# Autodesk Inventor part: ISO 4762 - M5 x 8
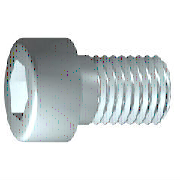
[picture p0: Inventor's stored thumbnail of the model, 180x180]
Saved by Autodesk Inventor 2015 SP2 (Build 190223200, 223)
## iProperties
IsCustomPart: 0
Created: 2012-02
Part Number: ISO 4762 - M5 x 8
Material: Edelstahl, 440C
Description: Innensechskantschraube
Document SubType Name: Modeling
Standard: ISO 4762
Designer: Dan
Standard Revision: 1998
Standards Organization: DIN
Language: de-DE
Size Designation: M5 x 8
Categories: <MemberInstance><Categories><Category DisplayName="Verbindungselemente" InternalName="e4da775c-781d-43d5-af7c-5136215cf5a6" Mnemonic="FSTN"><Category DisplayNam
Density: 7.75 g/cm^3
Appearance: Halbpoliert
Author: Dan
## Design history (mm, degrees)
sketch "Skizze1"
  geometry: L1 (-1.167, 0)-(8, 0); L2 (8, 0)-(8, 2.5); L3 (8, 2.5)-(2, 2.5); L4 (2, 2.5)-(1.509, 2.5); L5 (1.509, 2.5)-(0, 2.5); L6 (0, 2.5)-(0, 4.25); L7 (0, 4.25)-(-5, 4.25); L8 (-5, 4.25)-(-5, 2.309); L9 (-5, 2.309)-(-2.5, 2.309); L10 (-2.5, 2.309)-(-1.167, 0); L11 (-7.6, 0)-(10.6, 0) reference; L12 (0, -0.85)-(0, 5.1) reference; L13 (2, 2.5)-(0, 2.5)
  constraints: 22 end point, 6 parallel, 2 collinear, 2 perpendicular, 1 horizontal, 1 point on line
  dimensions: "d1" = 6 distance from line of L3.end L2 (= GEL); "d2" = 0.49086 distance of L4.end L3.end (computed from GAL); "d3" = 5 distance between parallel lines of L8 L6 (= KOH); "d4" = 2.5 distance of L8.end L9.end (= INTI); "d5" = 60 deg angle of L10 L1; "d6" = 5 diameter of L3 L1 (= GD); "d7" = 5 diameter of L5 L1 (= BDM); "d8" = 4.6188 diameter of L9 L1 (= 1.1547 x SW); "d9" = 8.5 diameter of L7 L1 (= KOD); "d26" = 8 distance between parallel lines of L12 L2 (= NLG)
revolve "Körper" sketch "Skizze1" stored, may be unused: angle "d10" = 90 deg
sketch "Skizze2"
  geometry: L1 (0, -5.95)-(0, 5.95) reference; L2 (-5.95, 0)-(5.95, 0) reference; L3 (2.309, 0)-(1.155, -2); L4 (1.155, -2)-(-1.155, -2); L5 (-1.155, -2)-(-2.309, 0); L6 (-2.309, 0)-(-1.155, 2); L7 (-1.155, 2)-(1.155, 2); L8 (1.155, 2)-(2.309, 0); 2 further points
  constraints: 12 end point, 1 coincident, 1 horizontal alignment, 1 point on line, 12 other
extrude "Loch" join sketch "Skizze2" stored distance "d11" = 10; taper "d12" = 0 deg
workplane "Work Plane1"
fillet "Fillet2" dims "d30" = 0.1 (= R)
body "Solid1"
fillet "Rundung1" dims "d17" = 0.5 (= RR)
feature "Gewinde" dims "d13" = 6 (= GEL), "d14" = 0
chamfer "Fase1" distance "d15" = 0.49076 (= -0.5 x SPD + 0.5 x GD); stored, may be unused: second distance "d16" = 0.49076 (= GUL), angle "d27" = 45 deg
other parameters: "GD" = 5 [user parameter; used in 2 equation terms], "NLG" = 8 [user parameter; used in 1 equation term], "GEL" = 6 [user parameter; used in 2 equation terms], "KOD" = 8.5 [user parameter; used in 1 equation term], "KOH" = 5 [user parameter; used in 1 equation term], "INTI" = 2.5 [user parameter; used in 1 equation term], "GAL" = 0.49076 (= 0.61345 x PTC) [user parameter; used in 1 equation term], "GUL" = 0.49076 (= 0.61345 x PTC) [user parameter; used in 1 equation term], "BDM" = 5 (= NND) [user parameter; used in 1 equation term], "SW" = 4 [user parameter; used in 2 equation terms], "RR" = 0.5 [user parameter; used in 1 equation term], "SPD" = 4.01848 (= NND - 1.2269 x PTC) [user parameter; used in 1 equation term], "d19" = 0, "d28" = 0, "d29" = 0, "R" = 0.1 [user parameter; used in 1 equation term], "TOA" = 30 deg [user parameter], "GD1" = 4.01848 (= THREADDIA - 1.2269 x PTC) [user parameter], "THREADDIA" = 5 [user parameter; used in 1 equation term], "FAWI" = 45 deg [user parameter], "TPU" = 12.5 (computed from PTC) [user parameter], "PTC" = 0.8 [user parameter; used in 5 equation terms], "NND" = 5 [user parameter; used in 2 equation terms], "E0" = 4.62 (= 1.155 x SW) [user parameter]
